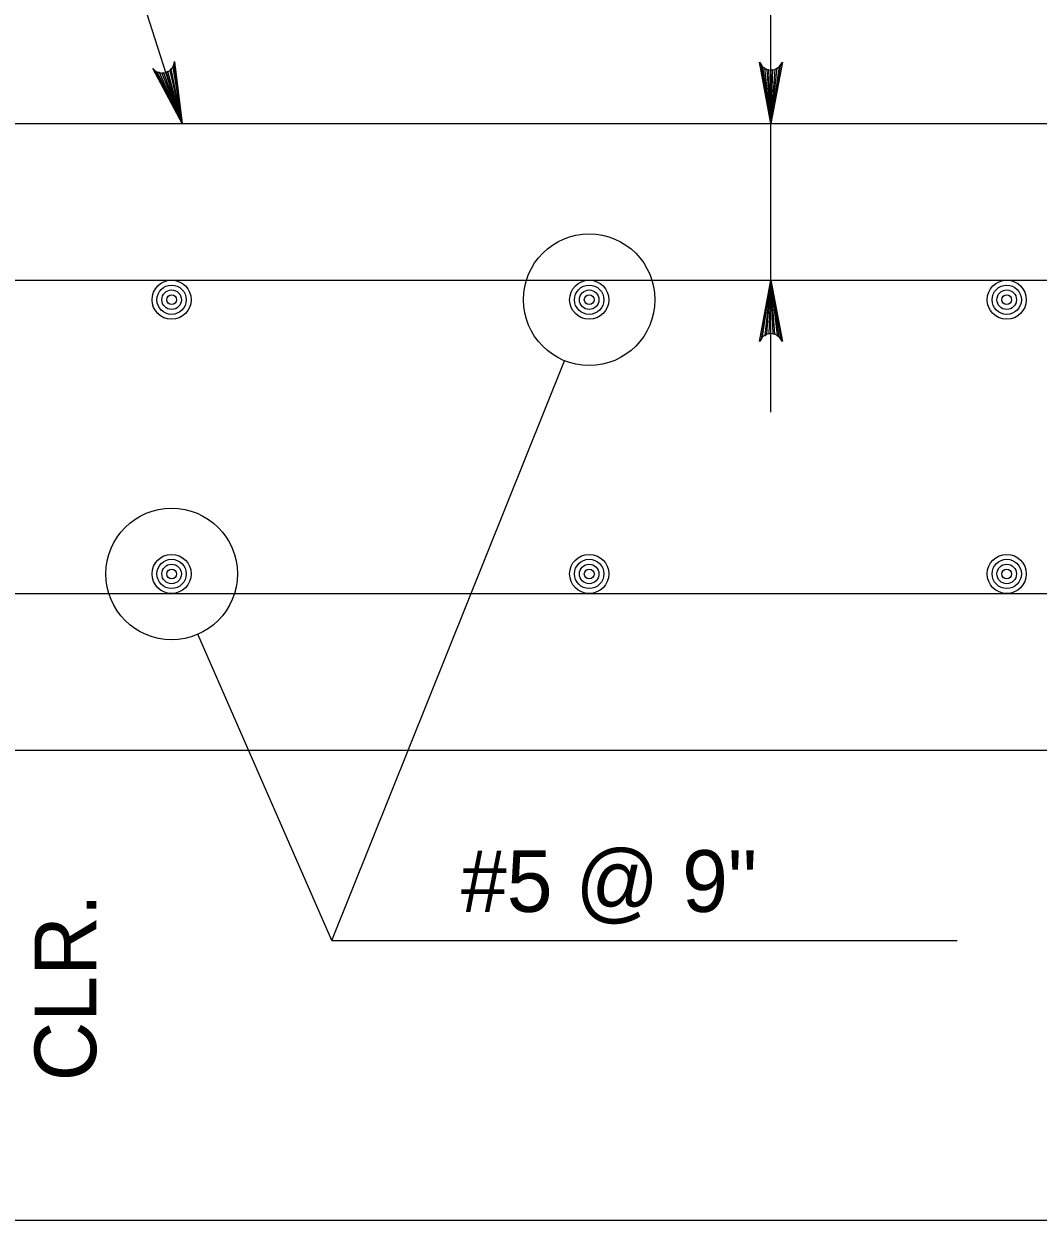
# Model space of a CAD drawing. Extents: x 636530 to 644067, y 294168 to 299122.
# Drawn here: x 639563.4 to 639612.8, y 297369.6 to 297427.8 of the extents above; entities that cross this region are included whole.
import ezdxf

# ---------------------------------------------------------------- set-up
doc = ezdxf.new("R2010")
doc.units = 0
doc.layers.add('1', color=7, linetype='Continuous')

msp = doc.modelspace()

# ---------------------------------------------------------------- linework, layer by layer
at = {"layer": '1'}
for p, q in [((639599.798, 297408.927), (639599.798, 297443.322)), ((639571.157, 297422.965), (639565.425, 297440.871)), ((639474.014, 297422.965), (639616.356, 297422.965)), ((639540.156, 297422.965), (639695.523, 297422.965)), ((639547.776, 297415.345), (639715.416, 297415.345)), ((639590.956, 297414.394), (639590.956, 297414.394)), ((639578.426, 297383.229), (639589.763, 297411.425)), ((639570.636, 297401.056), (639570.636, 297401.056)), ((639547.776, 297400.105), (639715.416, 297400.105)), ((639578.426, 297383.229), (639571.917, 297398.124)), ((639540.156, 297392.485), (639695.523, 297392.485)), ((639578.426, 297383.229), (639608.87, 297383.229)), ((639524.916, 297369.625), (639738.276, 297369.625))]:
    msp.add_line(p, q, dxfattribs=at)
for points in [[(639571.157, 297422.965), (639569.715, 297425.636), (639569.826, 297425.55), (639569.937, 297425.465), (639570.05, 297425.439), (639570.163, 297425.413), (639570.264, 297425.427), (639570.364, 297425.442), (639570.454, 297425.488), (639570.544, 297425.535), (639570.621, 297425.622), (639570.699, 297425.709), (639570.739, 297425.843), (639570.78, 297425.977), (639571.157, 297422.965), (639570.739, 297425.843), (639570.699, 297425.709), (639571.157, 297422.965), (639570.621, 297425.622), (639570.544, 297425.535), (639571.157, 297422.965), (639570.454, 297425.488), (639570.364, 297425.442), (639571.157, 297422.965), (639570.264, 297425.427), (639570.163, 297425.413), (639571.157, 297422.965), (639570.05, 297425.439), (639569.937, 297425.465), (639571.157, 297422.965), (639569.826, 297425.55)], [(639599.798, 297422.965), (639599.239, 297425.948), (639599.319, 297425.833), (639599.398, 297425.718), (639599.498, 297425.659), (639599.598, 297425.6), (639599.698, 297425.583), (639599.798, 297425.565), (639599.898, 297425.583), (639599.998, 297425.6), (639600.098, 297425.659), (639600.198, 297425.718), (639600.278, 297425.833), (639600.358, 297425.948), (639599.798, 297422.965), (639600.278, 297425.833), (639600.198, 297425.718), (639599.798, 297422.965), (639600.098, 297425.659), (639599.998, 297425.6), (639599.798, 297422.965), (639599.898, 297425.583), (639599.798, 297425.565), (639599.798, 297422.965), (639599.698, 297425.583), (639599.598, 297425.6), (639599.798, 297422.965), (639599.498, 297425.659), (639599.398, 297425.718), (639599.798, 297422.965), (639599.319, 297425.833)], [(639599.798, 297415.345), (639600.358, 297412.363), (639600.278, 297412.478), (639600.198, 297412.593), (639600.098, 297412.652), (639599.998, 297412.711), (639599.898, 297412.728), (639599.798, 297412.745), (639599.698, 297412.728), (639599.598, 297412.711), (639599.498, 297412.652), (639599.398, 297412.593), (639599.319, 297412.478), (639599.239, 297412.363), (639599.798, 297415.345), (639599.319, 297412.478), (639599.398, 297412.593), (639599.798, 297415.345), (639599.498, 297412.652), (639599.598, 297412.711), (639599.798, 297415.345), (639599.698, 297412.728), (639599.798, 297412.745), (639599.798, 297415.345), (639599.898, 297412.728), (639599.998, 297412.711), (639599.798, 297415.345), (639600.098, 297412.652), (639600.198, 297412.593), (639599.798, 297415.345), (639600.278, 297412.478)]]:
    msp.add_lwpolyline(points, dxfattribs=at)
for centre, radius in [((639590.956, 297414.394), 3.2), ((639570.636, 297414.394), 0.952), ((639570.636, 297414.394), 0.714), ((639590.956, 297414.394), 0.952), ((639590.956, 297414.394), 0.714), ((639611.276, 297414.394), 0.952), ((639611.276, 297414.394), 0.714), ((639570.636, 297414.394), 0.476), ((639570.636, 297414.394), 0.238), ((639590.956, 297414.394), 0.476), ((639590.956, 297414.394), 0.238), ((639611.276, 297414.394), 0.476), ((639611.276, 297414.394), 0.238), ((639570.636, 297401.056), 3.2), ((639570.636, 297401.056), 0.952), ((639570.636, 297401.056), 0.714), ((639590.956, 297401.056), 0.952), ((639590.956, 297401.056), 0.714), ((639611.276, 297401.056), 0.952), ((639611.276, 297401.056), 0.714), ((639570.636, 297401.056), 0.476), ((639570.636, 297401.056), 0.238), ((639590.956, 297401.056), 0.476), ((639590.956, 297401.056), 0.238), ((639611.276, 297401.056), 0.476), ((639611.276, 297401.056), 0.238)]:
    msp.add_circle(centre, radius, dxfattribs=at)

# ---------------------------------------------------------------- texts
msp.add_text('#5 @ 9"', height=3, dxfattribs=at).set_placement((639584.713, 297384.617))
msp.add_text('CLR.', height=3, rotation=90, dxfattribs=at).set_placement((639566.966, 297376.377))

doc.saveas('drawing.dxf')
